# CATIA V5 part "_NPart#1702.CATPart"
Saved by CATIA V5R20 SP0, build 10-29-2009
Part number: Junta tórica
Revision: ANY
Definition: UNKNOWN
Nomenclature: Junta tórica
Source: Unknown
Bounding box of the stored display mesh (mm): x -10.34 to 10.34, y -1 to 1, z -10.5 to 10.5
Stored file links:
  C:\Users\Utente\Desktop\IO LAVORO\3D X SITO CF\CUMSA\3D files AE\AE 082430\_NPart#1702.CATPart
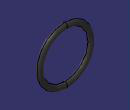
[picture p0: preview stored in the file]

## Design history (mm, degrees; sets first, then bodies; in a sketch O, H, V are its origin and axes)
Body1 "Revolución1" (main body)
  Solid1: solid without history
